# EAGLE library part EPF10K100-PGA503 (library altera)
EPF10K100 FLEX 10K family
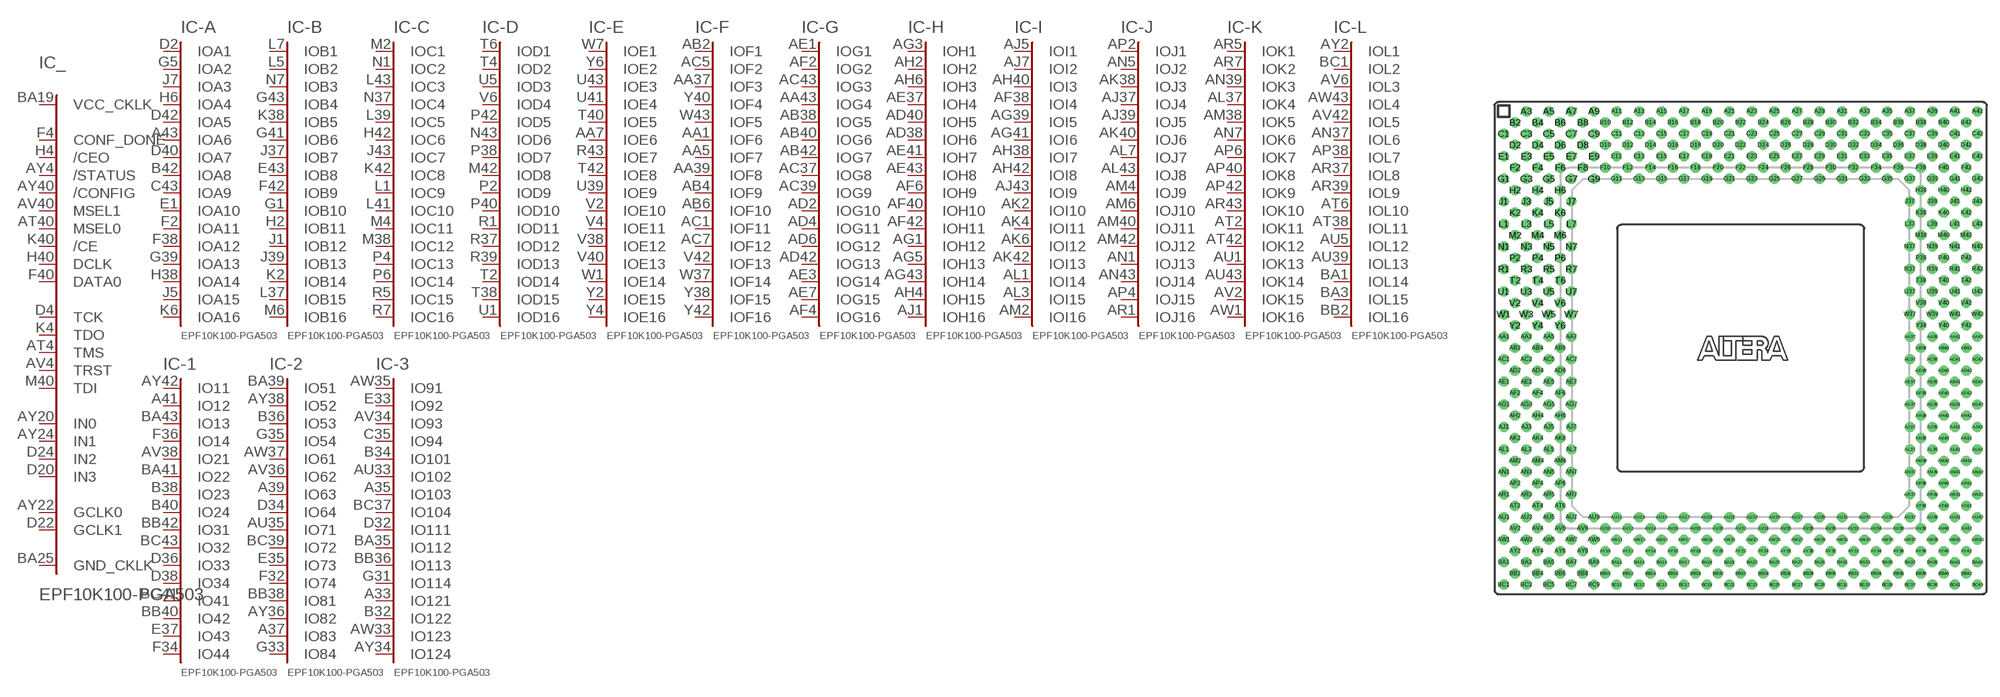
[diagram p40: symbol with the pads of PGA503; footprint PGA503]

Designator prefix IC; gates _=100P503C -A=A16 -B=B16 -C=C16 -D=D16 -E=E16 -F=F16 -G=G16 -H=H16 -I=I16 -J=J16 -K=K16 -L=L16 -1=IO44 -2=IO84 -3=IO124 -4=IO164 -5=IO204 -6=IO244 -7=IO284 -8=IO324 -9=IO364 -10=IO404 -11=IO444 -12=IO484 -13=IO524 1=VCCINT 2=VCCINT 3=VCCINT 4=VCCINT 5=VCCINT 6=VCCINT 7=VCCINT 8=VCCINT 9=VCCINT 10=VCCINT 11=VCCINT 12=VCCINT 13=VCCINT 14=VCCINT 15=VCCINT 16=VCCIO 17=VCCIO 18=VCCIO 19=VCCIO 20=VCCIO 21=VCCIO 22=VCCIO 23=VCCIO 24=VCCIO 25=VCCIO 26=VCCIO 27=VCCIO 28=VCCIO 29=VCCIO 30=VCCIO 31=VCCIO 32=VCCIO 33=VCCIO 34=VCCIO 35=VCCIO 36=VCCIO 37=VCCIO 38=VCCIO 39=VCCIO 40=VCCIO 41=GNDINT 42=GNDINT 43=GNDINT 44=GNDINT 45=GNDINT 46=GNDINT 47=GNDINT 48=GNDINT 49=GNDINT 50=GNDINT 51=GNDINT 52=GNDINT 53=GNDINT 54=GNDINT 55=GNDINT 56=GNDINT 58=GNDIO 59=GNDIO 60=GNDIO 61=GNDIO 62=GNDIO 63=GNDIO 64=GNDIO 65=GNDIO 66=GNDIO 67=GNDIO 68=GNDIO 69=GNDIO 70=GNDIO 71=GNDIO 72=GNDIO 73=GNDIO 74=GNDIO 75=GNDIO 76=GNDIO 77=GNDIO 78=GNDIO 79=GNDIO 80=GNDIO 81=GNDIO 82=GNDIO

## EPF10K100-PGA503 (OC_FARNELL: unknown; OC_NEWARK: unknown)  [PGA503]
A3  -13:IO502
A5  -12:IO474
A7  -11:IO432
A9  -11:IO412
A11  -10:IO393
A13  -9:IO363
A15  -9:IO333
A17  -8:IO312
A19  -8:IO292
A21  -7:IO263
A23  -7:IO253
A25  -6:IO222
A27  -5:IO201
A29  -5:IO171
A31  -4:IO154
A33  -3:IO121
A35  -3:IO103
A37  -2:IO83
A39  -2:IO63
A41  -1:IO12
A43  -A:IOA6
AA1  -F:IOF6
AA3  41:GND  pwr
AA5  -F:IOF7
AA7  -E:IOE6
AA37  -F:IOF3
AA39  -F:IOF8
AA41  58:GNDIO  pwr
AA43  -G:IOG4
AB2  -F:IOF1
AB4  -F:IOF9
AB6  -F:IOF10
AB38  -G:IOG5
AB40  -G:IOG6
AB42  -G:IOG7
AC1  -F:IOF11
AC3  1:VCC  pwr
AC5  -F:IOF2
AC7  -F:IOF12
AC37  -G:IOG8
AC39  -G:IOG9
AC41  17:VCCIO  pwr
AC43  -G:IOG3
AD2  -G:IOG10
AD4  -G:IOG11
AD6  -G:IOG12
AD38  -H:IOH6
AD40  -H:IOH5
AD42  -G:IOG13
AE1  -G:IOG1
AE3  -G:IOG14
AE5  18:VCCIO  pwr
AE7  -G:IOG15
AE37  -H:IOH4
AE39  42:GND  pwr
AE41  -H:IOH7
AE43  -H:IOH8
AF2  -G:IOG2
AF4  -G:IOG16
AF6  -H:IOH9
AF38  -I:IOI4
AF40  -H:IOH10
AF42  -H:IOH11
AG1  -H:IOH12
AG3  -H:IOH1
AG5  -H:IOH13
AG7  2:VCC  pwr
AG37  59:GNDIO  pwr
AG39  -I:IOI5
AG41  -I:IOI6
AG43  -H:IOH14
AH2  -H:IOH2
AH4  -H:IOH15
AH6  -H:IOH3
AH38  -I:IOI7
AH40  -I:IOI3
AH42  -I:IOI8
AJ1  -H:IOH16
AJ3  60:GNDIO  pwr
AJ5  -I:IOI1
AJ7  -I:IOI2
AJ37  -J:IOJ4
AJ39  -J:IOJ5
AJ41  19:VCCIO  pwr
AJ43  -I:IOI9
AK2  -I:IOI10
AK4  -I:IOI11
AK6  -I:IOI12
AK38  -J:IOJ3
AK40  -J:IOJ6
AK42  -I:IOI13
AL1  -I:IOI14
AL3  -I:IOI15
AL5  43:GND  pwr
AL7  -J:IOJ7
AL37  -K:IOK4
AL39  20:VCCIO  pwr
AL41  44:GND  pwr
AL43  -J:IOJ8
AM2  -I:IOI16
AM4  -J:IOJ9
AM6  -J:IOJ10
AM38  -K:IOK5
AM40  -J:IOJ11
AM42  -J:IOJ12
AN1  -J:IOJ13
AN3  61:GNDIO  pwr
AN5  -J:IOJ2
AN7  -K:IOK6
AN37  -L:IOL6
AN39  -K:IOK3
AN41  62:GNDIO  pwr
AN43  -J:IOJ14
AP2  -J:IOJ1
AP4  -J:IOJ15
AP6  -K:IOK7
AP38  -L:IOL7
AP40  -K:IOK8
AP42  -K:IOK9
AR1  -J:IOJ16
AR3  3:VCC  pwr
AR5  -K:IOK1
AR7  -K:IOK2
AR37  -L:IOL8
AR39  -L:IOL9
AR41  4:VCC  pwr
AR43  -K:IOK10
AT2  -K:IOK11
AT4  _:TMS
AT6  -L:IOL10
AT38  -L:IOL11
AT40  _:MSEL0  in
AT42  -K:IOK12
AU1  -K:IOK13
AU3  21:VCCIO  pwr
AU5  -L:IOL12
AU7  63:GNDIO  pwr
AU9  -13:IO492
AU11  -12:IO462
AU13  -11:IO421
AU15  -10:IO401
AU17  22:VCCIO  pwr
AU19  -8:IO321
AU21  -8:IO301
AU23  -7:IO273
AU25  -6:IO241
AU27  45:GND  pwr
AU29  -5:IO183
AU31  -4:IO141
AU33  -3:IO102
AU35  -2:IO71
AU37  5:VCC  pwr
AU39  -L:IOL13
AU41  64:GNDIO  pwr
AU43  -K:IOK14
AV2  -K:IOK15
AV4  _:TRST
AV6  -L:IOL3
AV8  -13:IO503
AV10  -12:IO472
AV12  -11:IO442
AV14  -9:IO361
AV16  -10:IO382
AV18  -9:IO341
AV20  -8:IO311
AV22  -7:IO281
AV24  -7:IO262
AV26  -6:IO233
AV28  -5:IO202
AV30  -4:IO163
AV32  -4:IO131
AV34  -3:IO93
AV36  -2:IO62
AV38  -1:IO21
AV40  _:MSEL1  in
AV42  -L:IOL5
AW1  -K:IOK16
AW3  23:VCCIO  pwr
AW5  6:VCC  pwr
AW7  -13:IO504
AW9  -12:IO473
AW11  -11:IO443
AW13  65:GNDIO  pwr
AW15  -10:IO392
AW17  -9:IO352
AW19  24:VCCIO  pwr
AW21  -8:IO303
AW23  -7:IO271
AW25  7:VCC  pwr
AW27  -6:IO223
AW29  -5:IO191
AW31  66:GNDIO  pwr
AW33  -3:IO123
AW35  -3:IO91
AW37  -2:IO61
AW39  46:GND  pwr
AW41  8:VCC  pwr
AW43  -L:IOL4
AY2  -L:IOL1
AY4  _:/STATUS  in
AY6  -13:IO513
AY8  -12:IO483
AY10  -12:IO453
AY12  -11:IO422
AY14  -10:IO402
AY16  -9:IO362
AY18  -9:IO331
AY20  _:IN0  in
AY22  _:GCLK0  in
AY24  _:IN1  in
AY26  -6:IO243
AY28  -6:IO213
AY30  -5:IO181
AY32  -4:IO153
AY34  -3:IO124
AY36  -2:IO82
AY38  -2:IO52
AY40  _:/CONFIG  in
AY42  -1:IO11
B2  -13:IO514
B4  -13:IO501
B6  -12:IO461
B8  -11:IO434
B10  -10:IO403
B12  -10:IO384
B14  -9:IO354
B16  -9:IO334
B18  -8:IO304
B20  -7:IO282
B22  -7:IO252
B24  -6:IO234
B26  -6:IO212
B28  -5:IO182
B30  -4:IO164
B32  -3:IO122
B34  -3:IO101
B36  -2:IO53
B38  -1:IO23
B40  -1:IO24
B42  -A:IOA8
BA1  -L:IOL14
BA3  -L:IOL15
BA5  -13:IO511
BA7  47:GND  pwr
BA9  25:VCCIO  pwr
BA11  67:GNDIO  pwr
BA13  48:GND  pwr
BA15  -10:IO372
BA17  9:VCC  pwr
BA19  _:VCC_CKLK  pas
BA21  68:GNDIO  pwr
BA23  69:GNDIO  pwr
BA25  _:GND_CKLK  pas
BA27  26:VCCIO  pwr
BA29  27:VCCIO  pwr
BA31  -5:IO172
BA33  -4:IO151
BA35  -3:IO112
BA37  28:VCCIO  pwr
BA39  -2:IO51
BA41  -1:IO22
BA43  -1:IO13
BB2  -L:IOL16
BB4  -13:IO523
BB6  -12:IO481
BB8  -12:IO451
BB10  -11:IO433
BB12  -11:IO413
BB14  -10:IO383
BB16  -9:IO351
BB18  -9:IO332
BB20  -8:IO313
BB22  -8:IO293
BB24  -7:IO264
BB26  -7:IO254
BB28  -6:IO224
BB30  -5:IO203
BB32  -5:IO173
BB34  -4:IO144
BB36  -3:IO113
BB38  -2:IO81
BB40  -1:IO42
BB42  -1:IO31
BC1  -L:IOL2
BC3  -13:IO521
BC5  -13:IO493
BC7  -12:IO463
BC9  -11:IO431
BC11  -11:IO414
BC13  -10:IO394
BC15  -10:IO373
BC17  -9:IO342
BC19  -8:IO322
BC21  -8:IO291
BC23  -7:IO283
BC25  -7:IO251
BC27  -6:IO231
BC29  -6:IO211
BC31  -5:IO193
BC33  -4:IO161
BC35  -4:IO133
BC37  -3:IO104
BC39  -2:IO72
BC41  -1:IO41
BC43  -1:IO32
C1  -13:IO522
C3  -13:IO512
C5  -13:IO491
C7  -12:IO464
C9  29:VCCIO  pwr
C11  10:VCC  pwr
C13  -10:IO371
C15  30:VCCIO  pwr
C17  49:GND  pwr
C19  -8:IO294
C21  70:GNDIO  pwr
C23  71:GNDIO  pwr
C25  31:VCCIO  pwr
C27  -5:IO192
C29  -5:IO174
C31  -4:IO132
C33  32:VCCIO  pwr
C35  -3:IO94
C37  33:VCCIO  pwr
C39  72:GNDIO  pwr
C41  73:GNDIO  pwr
C43  -A:IOA9
D2  -A:IOA1
D4  _:TCK
D6  -12:IO482
D8  -12:IO452
D10  -11:IO423
D12  -10:IO391
D14  -9:IO364
D16  -9:IO343
D18  -8:IO314
D20  _:IN3  in
D22  _:GCLK1  in
D24  _:IN2  in
D26  -6:IO214
D28  -5:IO184
D30  -4:IO143
D32  -3:IO111
D34  -2:IO64
D36  -1:IO33
D38  -1:IO34
D40  -A:IOA7
D42  -A:IOA5
E1  -A:IOA10
E3  50:GND  pwr
E5  51:GND  pwr
E7  -13:IO494
E9  -12:IO454
E11  -11:IO424
E13  74:GNDIO  pwr
E15  -9:IO353
E17  -8:IO323
E19  34:VCCIO  pwr
E21  -7:IO274
E23  -6:IO242
E25  52:GND  pwr
E27  -5:IO194
E29  -4:IO152
E31  75:GNDIO  pwr
E33  -3:IO92
E35  -2:IO73
E37  -1:IO43
E39  11:VCC  pwr
E41  35:VCCIO  pwr
E43  -B:IOB8
F2  -A:IOA11
F4  _:CONF_DONE  in
F6  -13:IO524
F8  -12:IO471
F10  -11:IO441
F12  -11:IO411
F14  -10:IO381
F16  -9:IO344
F18  -8:IO324
F20  -7:IO284
F22  -7:IO261
F24  -6:IO232
F26  -5:IO204
F28  -4:IO162
F30  -4:IO134
F32  -2:IO74
F34  -1:IO44
F36  -1:IO14
F38  -A:IOA12
F40  _:DATA0  in
F42  -B:IOB9
G1  -B:IOB10
G3  76:GNDIO  pwr
G5  -A:IOA2
G7  36:VCCIO  pwr
G9  -12:IO484
G11  -11:IO444
G13  -10:IO404
G15  -10:IO374
G17  77:GNDIO  pwr
G19  -8:IO302
G21  -7:IO272
G23  -6:IO244
G25  -6:IO221
G27  12:VCC  pwr
G29  -4:IO142
G31  -3:IO114
G33  -2:IO84
G35  -2:IO54
G37  53:GND  pwr
G39  -A:IOA13
G41  -B:IOB6
G43  -B:IOB4
H2  -B:IOB11
H4  _:/CEO  in
H6  -A:IOA4
H38  -A:IOA14
H40  _:DCLK  in
H42  -C:IOC6
J1  -B:IOB12
J3  54:GND  pwr
J5  -A:IOA15
J7  -A:IOA3
J37  -B:IOB7
J39  -B:IOB13
J41  55:GND  pwr
J43  -C:IOC7
K2  -B:IOB14
K4  _:TDO
K6  -A:IOA16
K38  -B:IOB5
K40  _:/CE  in
K42  -C:IOC8
L1  -C:IOC9
L3  37:VCCIO  pwr
L5  -B:IOB2
L7  -B:IOB1
L37  -B:IOB15
L39  -C:IOC5
L41  -C:IOC10
L43  -C:IOC3
M2  -C:IOC1
M4  -C:IOC11
M6  -B:IOB16
M38  -C:IOC12
M40  _:TDI
M42  -D:IOD8
N1  -C:IOC2
N3  78:GNDIO  pwr
N5  13:VCC  pwr
N7  -B:IOB3
N37  -C:IOC4
N39  79:GNDIO  pwr
N41  14:VCC  pwr
N43  -D:IOD6
P2  -D:IOD9
P4  -C:IOC13
P6  -C:IOC14
P38  -D:IOD7
P40  -D:IOD10
P42  -D:IOD5
R1  -D:IOD11
R3  80:GNDIO  pwr
R5  -C:IOC15
R7  -C:IOC16
R37  -D:IOD12
R39  -D:IOD13
R41  38:VCCIO  pwr
R43  -E:IOE7
T2  -D:IOD14
T4  -D:IOD2
T6  -D:IOD1
T38  -D:IOD15
T40  -E:IOE5
T42  -E:IOE8
U1  -D:IOD16
U3  39:VCCIO  pwr
U5  -D:IOD3
U7  56:GND  pwr
U37  40:VCCIO  pwr
U39  -E:IOE9
U41  -E:IOE4
U43  -E:IOE3
V2  -E:IOE10
V4  -E:IOE11
V6  -D:IOD4
V38  -E:IOE12
V40  -E:IOE13
V42  -F:IOF13
W1  -E:IOE14
W3  81:GNDIO  pwr
W5  16:VCCIO  pwr
W7  -E:IOE1
W37  -F:IOF14
W39  15:VCC  pwr
W41  82:GNDIO  pwr
W43  -F:IOF5
Y2  -E:IOE15
Y4  -E:IOE16
Y6  -E:IOE2
Y38  -F:IOF15
Y40  -F:IOF4
Y42  -F:IOF16

## Footprint PGA503 (pad centres in mm)
Pin Grid Array
drill 0.61 pad 1.016 round: A3 -24.13,26.67; A5 -21.59,26.67; A7 -19.05,26.67; A9 -16.51,26.67; A11 -13.97,26.67; A13 -11.43,26.67; A15 -8.89,26.67; A17 -6.35,26.67; A19 -3.81,26.67; A21 -1.27,26.67; A23 1.27,26.67; A25 3.81,26.67; A27 6.35,26.67; A29 8.89,26.67; A31 11.43,26.67; A33 13.97,26.67; A35 16.51,26.67; A37 19.05,26.67; A39 21.59,26.67; A41 24.13,26.67; A43 26.67,26.67; AA1 -26.67,1.27; AA3 -24.13,1.27; AA5 -21.59,1.27; AA7 -19.05,1.27; AA37 19.05,1.27; AA39 21.59,1.27; AA41 24.13,1.27; AA43 26.67,1.27; AB2 -25.4,0; AB4 -22.86,0; AB6 -20.32,0; AB38 20.32,0; AB40 22.86,0; AB42 25.4,0; AC1 -26.67,-1.27; AC3 -24.13,-1.27; AC5 -21.59,-1.27; AC7 -19.05,-1.27; AC37 19.05,-1.27; AC39 21.59,-1.27; AC41 24.13,-1.27; AC43 26.67,-1.27; AD2 -25.4,-2.54; AD4 -22.86,-2.54; AD6 -20.32,-2.54; AD38 20.32,-2.54; AD40 22.86,-2.54; AD42 25.4,-2.54; AE1 -26.67,-3.81; AE3 -24.13,-3.81; AE5 -21.59,-3.81; AE7 -19.05,-3.81; AE37 19.05,-3.81; AE39 21.59,-3.81; AE41 24.13,-3.81; AE43 26.67,-3.81; AF2 -25.4,-5.08; AF4 -22.86,-5.08; AF6 -20.32,-5.08; AF38 20.32,-5.08; AF40 22.86,-5.08; AF42 25.4,-5.08; AG1 -26.67,-6.35; AG3 -24.13,-6.35; AG5 -21.59,-6.35; AG7 -19.05,-6.35; AG37 19.05,-6.35; AG39 21.59,-6.35; AG41 24.13,-6.35; AG43 26.67,-6.35; AH2 -25.4,-7.62; AH4 -22.86,-7.62; AH6 -20.32,-7.62; AH38 20.32,-7.62; AH40 22.86,-7.62; AH42 25.4,-7.62; AJ1 -26.67,-8.89; AJ3 -24.13,-8.89; AJ5 -21.59,-8.89; AJ7 -19.05,-8.89; AJ37 19.05,-8.89; AJ39 21.59,-8.89; AJ41 24.13,-8.89; AJ43 26.67,-8.89; AK2 -25.4,-10.16; AK4 -22.86,-10.16; AK6 -20.32,-10.16; AK38 20.32,-10.16; AK40 22.86,-10.16; AK42 25.4,-10.16; AL1 -26.67,-11.43; AL3 -24.13,-11.43; AL5 -21.59,-11.43; AL7 -19.05,-11.43; AL37 19.05,-11.43; AL39 21.59,-11.43; AL41 24.13,-11.43; AL43 26.67,-11.43; AM2 -25.4,-12.7; AM4 -22.86,-12.7; AM6 -20.32,-12.7; AM38 20.32,-12.7; AM40 22.86,-12.7; AM42 25.4,-12.7; AN1 -26.67,-13.97; AN3 -24.13,-13.97; AN5 -21.59,-13.97; AN7 -19.05,-13.97; AN37 19.05,-13.97; AN39 21.59,-13.97; AN41 24.13,-13.97; AN43 26.67,-13.97; AP2 -25.4,-15.24; AP4 -22.86,-15.24; AP6 -20.32,-15.24; AP38 20.32,-15.24; AP40 22.86,-15.24; AP42 25.4,-15.24; AR1 -26.67,-16.51; AR3 -24.13,-16.51; AR5 -21.59,-16.51; AR7 -19.05,-16.51; AR37 19.05,-16.51; AR39 21.59,-16.51; AR41 24.13,-16.51; AR43 26.67,-16.51; AT2 -25.4,-17.78; AT4 -22.86,-17.78; AT6 -20.32,-17.78; AT38 20.32,-17.78; AT40 22.86,-17.78; AT42 25.4,-17.78; AU1 -26.67,-19.05; AU3 -24.13,-19.05; AU5 -21.59,-19.05; AU7 -19.05,-19.05; AU9 -16.51,-19.05; AU11 -13.97,-19.05; AU13 -11.43,-19.05; AU15 -8.89,-19.05; AU17 -6.35,-19.05; AU19 -3.81,-19.05; AU21 -1.27,-19.05; AU23 1.27,-19.05; AU25 3.81,-19.05; AU27 6.35,-19.05; AU29 8.89,-19.05; AU31 11.43,-19.05; AU33 13.97,-19.05; AU35 16.51,-19.05; AU37 19.05,-19.05; AU39 21.59,-19.05; AU41 24.13,-19.05; AU43 26.67,-19.05; AV2 -25.4,-20.32; AV4 -22.86,-20.32; AV6 -20.32,-20.32; AV8 -17.78,-20.32; AV10 -15.24,-20.32; AV12 -12.7,-20.32; AV14 -10.16,-20.32; AV16 -7.62,-20.32; AV18 -5.08,-20.32; AV20 -2.54,-20.32; AV22 0,-20.32; AV24 2.54,-20.32; AV26 5.08,-20.32; AV28 7.62,-20.32; AV30 10.16,-20.32; AV32 12.7,-20.32; AV34 15.24,-20.32; AV36 17.78,-20.32; AV38 20.32,-20.32; AV40 22.86,-20.32; AV42 25.4,-20.32; AW1 -26.67,-21.59; AW3 -24.13,-21.59; AW5 -21.59,-21.59; AW7 -19.05,-21.59; AW9 -16.51,-21.59; AW11 -13.97,-21.59; AW13 -11.43,-21.59; AW15 -8.89,-21.59; AW17 -6.35,-21.59; AW19 -3.81,-21.59; AW21 -1.27,-21.59; AW23 1.27,-21.59; AW25 3.81,-21.59; AW27 6.35,-21.59; AW29 8.89,-21.59; AW31 11.43,-21.59; AW33 13.97,-21.59; AW35 16.51,-21.59; AW37 19.05,-21.59; AW39 21.59,-21.59; AW41 24.13,-21.59; AW43 26.67,-21.59; AY2 -25.4,-22.86; AY4 -22.86,-22.86; AY6 -20.32,-22.86; AY8 -17.78,-22.86; AY10 -15.24,-22.86; AY12 -12.7,-22.86; AY14 -10.16,-22.86; AY16 -7.62,-22.86; AY18 -5.08,-22.86; AY20 -2.54,-22.86; AY22 0,-22.86; AY24 2.54,-22.86; AY26 5.08,-22.86; AY28 7.62,-22.86; AY30 10.16,-22.86; AY32 12.7,-22.86; AY34 15.24,-22.86; AY36 17.78,-22.86; AY38 20.32,-22.86; AY40 22.86,-22.86; AY42 25.4,-22.86; B2 -25.4,25.4; B4 -22.86,25.4; B6 -20.32,25.4; B8 -17.78,25.4; B10 -15.24,25.4; B12 -12.7,25.4; B14 -10.16,25.4; B16 -7.62,25.4; B18 -5.08,25.4; B20 -2.54,25.4; B22 0,25.4; B24 2.54,25.4; B26 5.08,25.4; B28 7.62,25.4; B30 10.16,25.4; B32 12.7,25.4; B34 15.24,25.4; B36 17.78,25.4; B38 20.32,25.4; B40 22.86,25.4; B42 25.4,25.4; BA1 -26.67,-24.13; BA3 -24.13,-24.13; BA5 -21.59,-24.13; BA7 -19.05,-24.13; BA9 -16.51,-24.13; BA11 -13.97,-24.13; BA13 -11.43,-24.13; BA15 -8.89,-24.13; BA17 -6.35,-24.13; BA19 -3.81,-24.13; BA21 -1.27,-24.13; BA23 1.27,-24.13; BA25 3.81,-24.13; BA27 6.35,-24.13; BA29 8.89,-24.13; BA31 11.43,-24.13; BA33 13.97,-24.13; BA35 16.51,-24.13; BA37 19.05,-24.13; BA39 21.59,-24.13; BA41 24.13,-24.13; BA43 26.67,-24.13; BB2 -25.4,-25.4; BB4 -22.86,-25.4; BB6 -20.32,-25.4; BB8 -17.78,-25.4; BB10 -15.24,-25.4; BB12 -12.7,-25.4; BB14 -10.16,-25.4; BB16 -7.62,-25.4; BB18 -5.08,-25.4; BB20 -2.54,-25.4; BB22 0,-25.4; BB24 2.54,-25.4; BB26 5.08,-25.4; BB28 7.62,-25.4; BB30 10.16,-25.4; BB32 12.7,-25.4; BB34 15.24,-25.4; BB36 17.78,-25.4; BB38 20.32,-25.4; BB40 22.86,-25.4; BB42 25.4,-25.4; BC1 -26.67,-26.67; BC3 -24.13,-26.67; BC5 -21.59,-26.67; BC7 -19.05,-26.67; BC9 -16.51,-26.67; BC11 -13.97,-26.67; BC13 -11.43,-26.67; BC15 -8.89,-26.67; BC17 -6.35,-26.67; BC19 -3.81,-26.67; BC21 -1.27,-26.67; BC23 1.27,-26.67; BC25 3.81,-26.67; BC27 6.35,-26.67; BC29 8.89,-26.67; BC31 11.43,-26.67; BC33 13.97,-26.67; BC35 16.51,-26.67; BC37 19.05,-26.67; BC39 21.59,-26.67; BC41 24.13,-26.67; BC43 26.67,-26.67; C1 -26.67,24.13; C3 -24.13,24.13; C5 -21.59,24.13; C7 -19.05,24.13; C9 -16.51,24.13; C11 -13.97,24.13; C13 -11.43,24.13; C15 -8.89,24.13; C17 -6.35,24.13; C19 -3.81,24.13; C21 -1.27,24.13; C23 1.27,24.13; C25 3.81,24.13; C27 6.35,24.13; C29 8.89,24.13; C31 11.43,24.13; C33 13.97,24.13; C35 16.51,24.13; C37 19.05,24.13; C39 21.59,24.13; C41 24.13,24.13; C43 26.67,24.13; D2 -25.4,22.86; D4 -22.86,22.86; D6 -20.32,22.86; D8 -17.78,22.86; D10 -15.24,22.86; D12 -12.7,22.86; D14 -10.16,22.86; D16 -7.62,22.86; D18 -5.08,22.86; D20 -2.54,22.86; D22 0,22.86; D24 2.54,22.86; D26 5.08,22.86; D28 7.62,22.86; D30 10.16,22.86; D32 12.7,22.86; D34 15.24,22.86; D36 17.78,22.86; D38 20.32,22.86; D40 22.86,22.86; D42 25.4,22.86; E1 -26.67,21.59; E3 -24.13,21.59; E5 -21.59,21.59; E7 -19.05,21.59; E9 -16.51,21.59; E11 -13.97,21.59; E13 -11.43,21.59; E15 -8.89,21.59; E17 -6.35,21.59; E19 -3.81,21.59; E21 -1.27,21.59; E23 1.27,21.59; E25 3.81,21.59; E27 6.35,21.59; E29 8.89,21.59; E31 11.43,21.59; E33 13.97,21.59; E35 16.51,21.59; E37 19.05,21.59; E39 21.59,21.59; E41 24.13,21.59; E43 26.67,21.59; F2 -25.4,20.32; F4 -22.86,20.32; F6 -20.32,20.32; F8 -17.78,20.32; F10 -15.24,20.32; F12 -12.7,20.32; F14 -10.16,20.32; F16 -7.62,20.32; F18 -5.08,20.32; F20 -2.54,20.32; F22 0,20.32; F24 2.54,20.32; F26 5.08,20.32; F28 7.62,20.32; F30 10.16,20.32; F32 12.7,20.32; F34 15.24,20.32; F36 17.78,20.32; F38 20.32,20.32; F40 22.86,20.32; F42 25.4,20.32; G1 -26.67,19.05; G3 -24.13,19.05; G5 -21.59,19.05; G7 -19.05,19.05; G9 -16.51,19.05; G11 -13.97,19.05; G13 -11.43,19.05; G15 -8.89,19.05; G17 -6.35,19.05; G19 -3.81,19.05; G21 -1.27,19.05; G23 1.27,19.05; G25 3.81,19.05; G27 6.35,19.05; G29 8.89,19.05; G31 11.43,19.05; G33 13.97,19.05; G35 16.51,19.05; G37 19.05,19.05; G39 21.59,19.05; G41 24.13,19.05; G43 26.67,19.05; H2 -25.4,17.78; H4 -22.86,17.78; H6 -20.32,17.78; H38 20.32,17.78; H40 22.86,17.78; H42 25.4,17.78; J1 -26.67,16.51; J3 -24.13,16.51; J5 -21.59,16.51; J7 -19.05,16.51; J37 19.05,16.51; J39 21.59,16.51; J41 24.13,16.51; J43 26.67,16.51; K2 -25.4,15.24; K4 -22.86,15.24; K6 -20.32,15.24; K38 20.32,15.24; K40 22.86,15.24; K42 25.4,15.24; L1 -26.67,13.97; L3 -24.13,13.97; L5 -21.59,13.97; L7 -19.05,13.97; L37 19.05,13.97; L39 21.59,13.97; L41 24.13,13.97; L43 26.67,13.97; M2 -25.4,12.7; M4 -22.86,12.7; M6 -20.32,12.7; M38 20.32,12.7; M40 22.86,12.7; M42 25.4,12.7; N1 -26.67,11.43; N3 -24.13,11.43; N5 -21.59,11.43; N7 -19.05,11.43; N37 19.05,11.43; N39 21.59,11.43; N41 24.13,11.43; N43 26.67,11.43; P2 -25.4,10.16; P4 -22.86,10.16; P6 -20.32,10.16; P38 20.32,10.16; P40 22.86,10.16; P42 25.4,10.16; R1 -26.67,8.89; R3 -24.13,8.89; R5 -21.59,8.89; R7 -19.05,8.89; R37 19.05,8.89; R39 21.59,8.89; R41 24.13,8.89; R43 26.67,8.89; T2 -25.4,7.62; T4 -22.86,7.62; T6 -20.32,7.62; T38 20.32,7.62; T40 22.86,7.62; T42 25.4,7.62; U1 -26.67,6.35; U3 -24.13,6.35; U5 -21.59,6.35; U7 -19.05,6.35; U37 19.05,6.35; U39 21.59,6.35; U41 24.13,6.35; U43 26.67,6.35; V2 -25.4,5.08; V4 -22.86,5.08; V6 -20.32,5.08; V38 20.32,5.08; V40 22.86,5.08; V42 25.4,5.08; W1 -26.67,3.81; W3 -24.13,3.81; W5 -21.59,3.81; W7 -19.05,3.81; W37 19.05,3.81; W39 21.59,3.81; W41 24.13,3.81; W43 26.67,3.81; Y2 -25.4,2.54; Y4 -22.86,2.54; Y6 -20.32,2.54; Y38 20.32,2.54; Y40 22.86,2.54; Y42 25.4,2.54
